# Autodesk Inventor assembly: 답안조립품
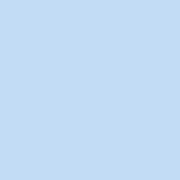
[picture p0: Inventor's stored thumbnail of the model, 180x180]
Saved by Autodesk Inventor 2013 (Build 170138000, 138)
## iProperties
Created: 2019-01
Part Number: 답안조립품
Document SubType Name: Assembly
Designer: Administrator
Author: Administrator
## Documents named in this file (1)
- C:\Users\Administrator\Desktop\490107V1010\답안조립품.iam
